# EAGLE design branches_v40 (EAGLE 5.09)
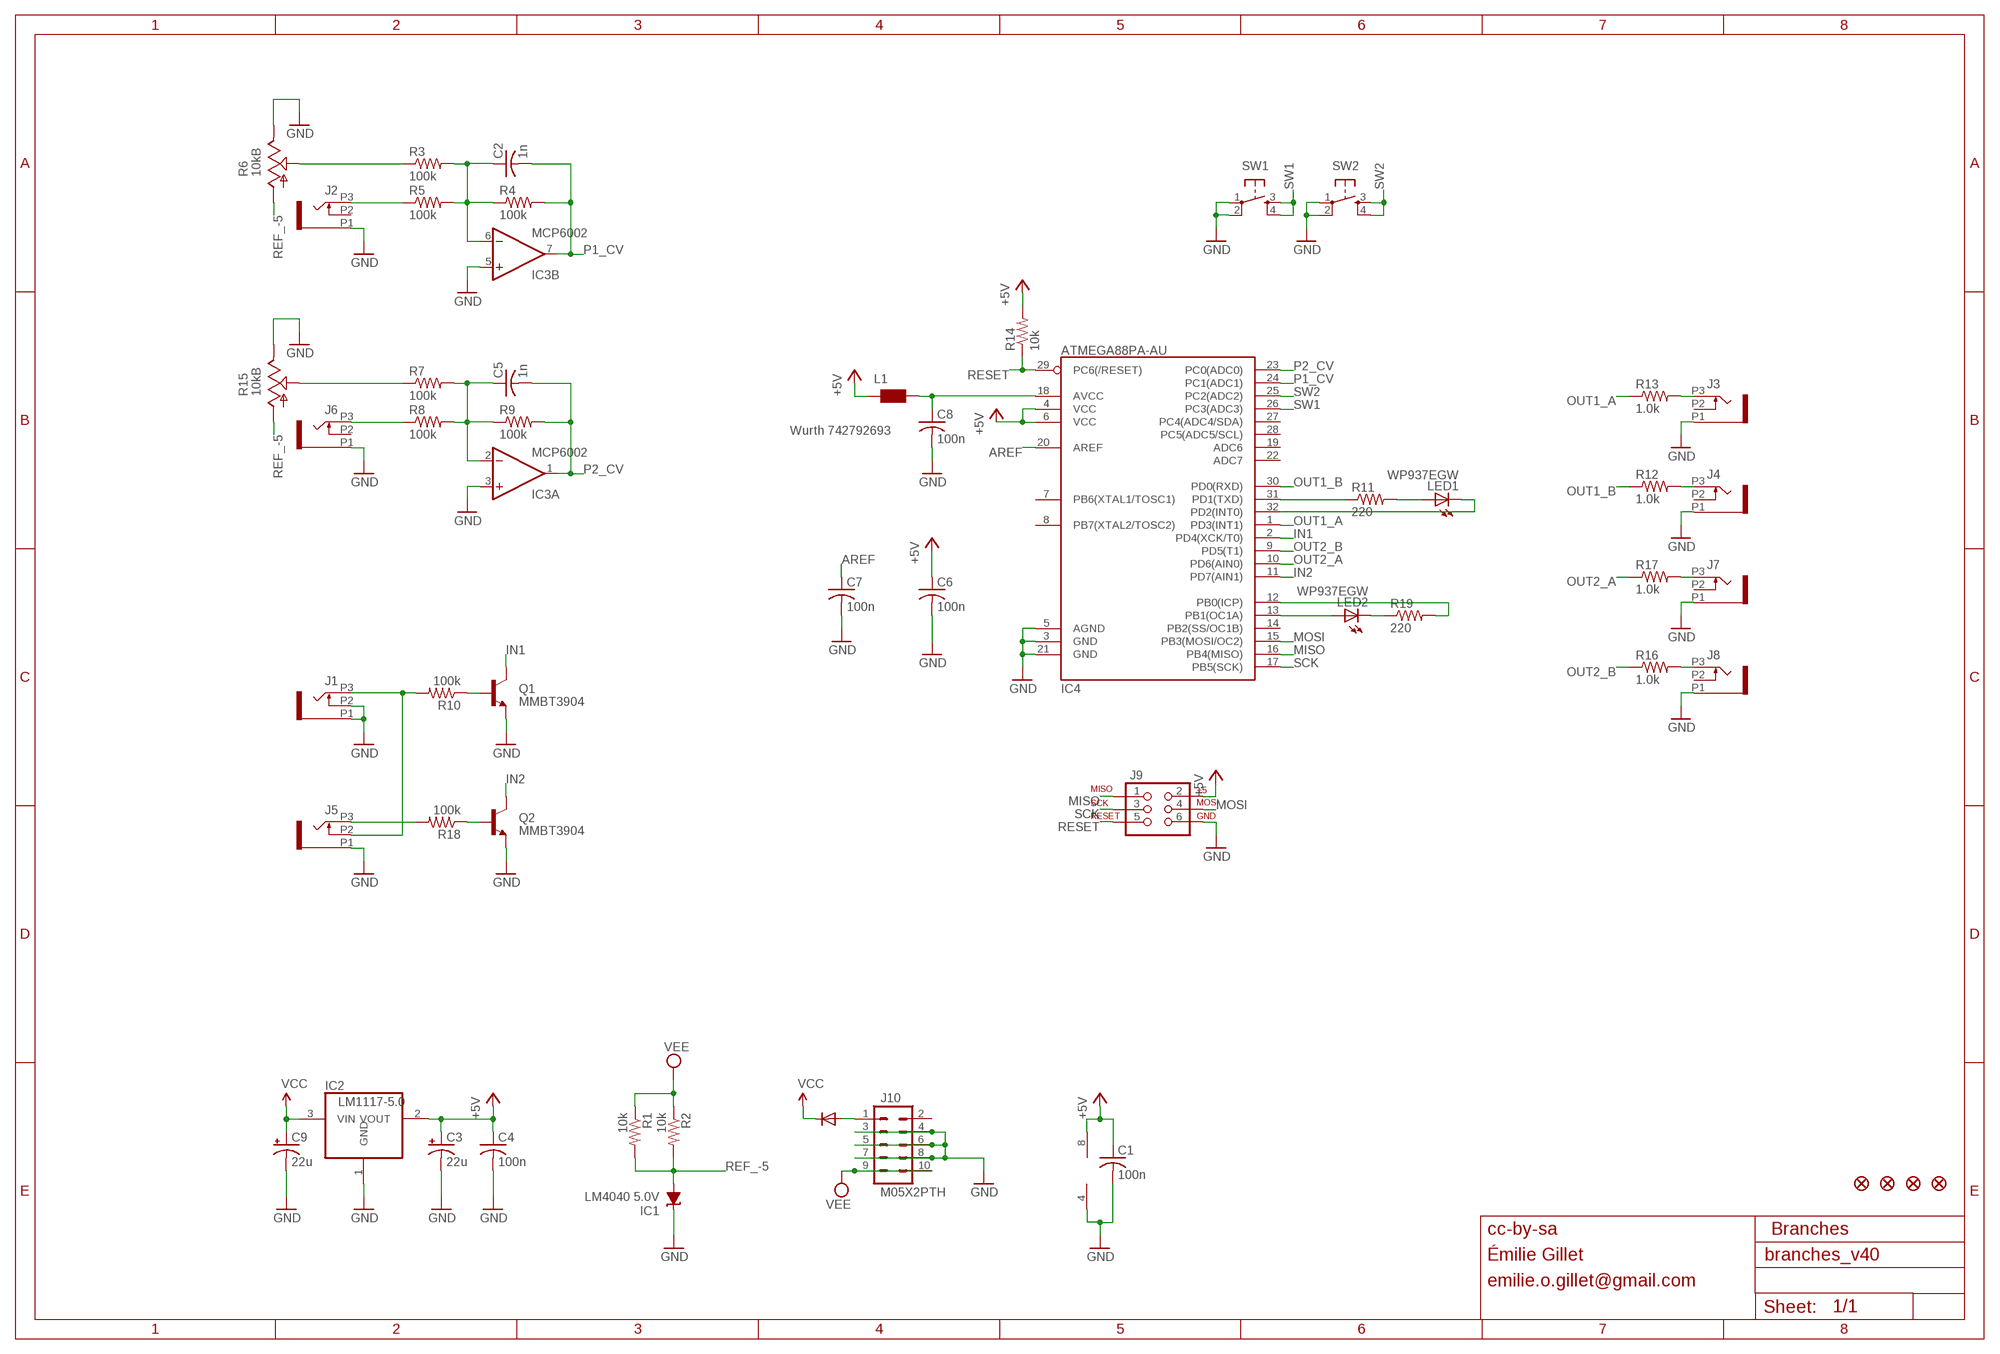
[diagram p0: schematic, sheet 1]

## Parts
C1  100n  C-USC0603  [C0603]
C2  1n  C-USC0603  [C0603]
C3  22u  CPOL-USC  [PANASONIC_C]
C4  100n  C-USC0603  [C0603]
C5  1n  C-USC0603  [C0603]
C6  100n  C-USC0603  [C0603]
C7  100n  C-USC0603  [C0603]
C8  100n  C-USC0603  [C0603]
C9  22u  CPOL-USC  [PANASONIC_C]
D1  1N5819HW  DIODE-SOD123  [SOD123]
F1  FIDUCIAL1X2  [FIDUCIAL-1X2]
F2  FIDUCIAL1X2  [FIDUCIAL-1X2]
F3  FIDUCIAL1X2  [FIDUCIAL-1X2]
F4  FIDUCIAL1X2  [FIDUCIAL-1X2]
IC1  LM4040 5.0V  LM4041C12DBZ  [DBZ_R-PDSO-G3]
IC2  LM1117-5.0  REG1117  [SOT223]
IC3  MCP6002  TL072D  [SO08]
IC4  ATMEGA88PA-AU  ATMEGA168  [TQFP32-08]
J1  PJ301_THONKICONN6  [WQP_PJ_301M6]
J2  PJ301_THONKICONN6  [WQP_PJ_301M6]
J3  PJ301_THONKICONN6  [WQP_PJ_301M6]
J4  PJ301_THONKICONN6  [WQP_PJ_301M6]
J5  PJ301_THONKICONN6  [WQP_PJ_301M6]
J6  PJ301_THONKICONN6  [WQP_PJ_301M6]
J7  PJ301_THONKICONN6  [WQP_PJ_301M6]
J8  PJ301_THONKICONN6  [WQP_PJ_301M6]
J9  AVR_SPI_PRG_6PTH  [2X3]
J10  M05X2PTH  [AVR_ICSP]
L1  WE-CBF_0603  [0603]
LED1  WP937EGW  LED3MM  [LED3MM]
LED2  WP937EGW  LED3MM  [LED3MM]
Q1  MMBT3904  MMBT3904LT1-NPN-SOT23-BEC  [SOT23-BEC]
Q2  MMBT3904  MMBT3904LT1-NPN-SOT23-BEC  [SOT23-BEC]
R1  10k  R-US_R0603  [R0603]
R2  10k  R-US_R0603  [R0603]
R3  100k  R-US_R0603  [R0603]
R4  100k  R-US_R0603  [R0603]
R5  100k  R-US_R0603  [R0603]
R6  10kB  POT_USVERTICAL_PS  [ALPS_POT_VERTICAL_PS]
R7  100k  R-US_R0603  [R0603]
R8  100k  R-US_R0603  [R0603]
R9  100k  R-US_R0603  [R0603]
R10  100k  R-US_R0603  [R0603]
R11  220  R-US_R0603  [R0603]
R12  1.0k  R-US_R0603  [R0603]
R13  1.0k  R-US_R0603  [R0603]
R14  10k  R-US_R0603  [R0603]
R15  10kB  POT_USVERTICAL_PS  [ALPS_POT_VERTICAL_PS]
R16  1.0k  R-US_R0603  [R0603]
R17  1.0k  R-US_R0603  [R0603]
R18  100k  R-US_R0603  [R0603]
R19  220  R-US_R0603  [R0603]
SW1  TAC_SWITCHPTH  [TACTILE-PTH]
SW2  TAC_SWITCHPTH  [TACTILE-PTH]

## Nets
+5V: C1.1 C3.+ C4.1 C6.1 IC2.2(VOUT) IC3.8(P:V+) IC4.4(VCC) IC4.6(VCC) J9.2 L1.1 R14.2
AREF: C7.1 IC4.20(AREF)
GATE1_IN: J1.P3 J5.P2 R10.2
GATE2_IN: J5.P3 R18.2
GND: C1.2 C3.- C4.2 C6.2 C7.2 C8.2 C9.- IC1.1(C) IC2.1(GND) IC3.3(A:+IN) IC3.4(P:V-) IC3.5(B:+IN) IC4.3(GND) IC4.5(AGND) IC4.21(GND) J1.P1 J1.P2 J2.P1 J3.P1 J4.P1 J5.P1 J6.P1 J7.P1 J8.P1 J9.6 J10.3 J10.4 J10.5 J10.6 J10.7 J10.8 Q1.E Q2.E R6.P$1(E) R15.P$1(E) SW1.1 SW1.2 SW2.1 SW2.2
IN1: IC4.2(PD4(XCK/T0)) Q1.C
IN2: IC4.11(PD7(AIN1)) Q2.C
MISO: IC4.16(PB4(MISO)) J9.1
MOSI: IC4.15(PB3(MOSI/OC2)) J9.4
N$1: Q1.B R10.1
N$2: Q2.B R18.1
N$3: D1.A J10.1
N$4: C5.1 IC3.2(A:-IN) R7.2 R8.2 R9.1
N$6: J8.P3 R16.2
N$8: R7.1 R15.P$2(S)
N$9: R3.1 R6.P$2(S)
N$10: J2.P3 R5.1
N$11: J6.P3 R8.1
N$13: IC4.31(PD1(TXD)) R11.1
N$14: LED1.A R11.2
N$15: IC4.32(PD2(INT0)) LED1.K(C)
N$16: IC4.13(PB1(OC1A)) LED2.A
N$17: LED2.K(C) R19.1
N$18: IC4.12(PB0(ICP)) R19.2
N$29: C2.1 IC3.6(B:-IN) R3.2 R4.1 R5.2
N$34: J3.P3 R13.2
N$35: J4.P3 R12.2
N$36: J7.P3 R17.2
N$39: C8.1 IC4.18(AVCC) L1.2
OUT1_A: IC4.1(PD3(INT1)) R13.1
OUT1_B: IC4.30(PD0(RXD)) R12.1
OUT2_A: IC4.10(PD6(AIN0)) R17.1
OUT2_B: IC4.9(PD5(T1)) R16.1
P1_CV: C2.2 IC3.7(B:OUT) IC4.24(PC1(ADC1)) R4.2
P2_CV: C5.2 IC3.1(A:OUT) IC4.23(PC0(ADC0)) R9.2
REF_-5: IC1.2(A) R1.2 R2.2 R6.P$3(A) R15.P$3(A)
RESET: IC4.29(PC6(/RESET)) J9.5 R14.1
SCK: IC4.17(PB5(SCK)) J9.3
SW1: IC4.26(PC3(ADC3)) SW1.3 SW1.4
SW2: IC4.25(PC2(ADC2)) SW2.3 SW2.4
VCC: C9.+ D1.C IC2.3(VIN)
VEE: J10.9 J10.10 R1.1 R2.1
Unconnected: IC4.7(PB6(XTAL1/TOSC1)) IC4.8(PB7(XTAL2/TOSC2)) IC4.14(PB2(SS/OC1B)) IC4.19(ADC6) IC4.22(ADC7) IC4.27(PC4(ADC4/SDA)) IC4.28(PC5(ADC5/SCL)) J2.P2 J3.P2 J4.P2 J6.P2 J7.P2 J8.P2 J10.2

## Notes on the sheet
- Wurth 742792693
- cc-by-sa | Branches
- Émilie Gillet
- emilie.o.gillet@gmail.com

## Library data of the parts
C1 C2 C4-C8 = rcl:C-US: CAPACITOR, American symbol
C3 C9 = rcl:CPOL-US: POLARIZED CAPACITOR, American symbol
D1 = diode:DIODE-: DIODE
F1-F4 = SparkFun:FIDUCIAL: Fiducial Alignment Points
IC1 = texas:LM4041: PRECISION MICROPOWER SHUNT VOLTAGE REFERENCE
IC2 = og-vreg:REG1117: 800mA and 1A Low Dropout (LDO) Positive Regulator 1.8V, 2.5V, 2.85V, 3.3V, 5V, and Adj
IC3 = og-linear:TL072: OP AMP
IC4 = SparkFun:ATMEGA168
J1-J8 = og-pj301:PJ301_THONKICONN
J9 = SparkFun:AVR_SPI_PRG_6: AVR ISP 6 Pin This is the reduced ISP connector for AVR programming. Common on Arduino. This footprint will take up less PCB space and can be used with a 10-pin to 6-pin adapter such as SKU: BOB-08508
J10 = og-header:M05X2: Header 5x2 Standard 10-pin dual row 0.1" header. Commonly used with AVR-ISP. Use with Spark Fun Electronics SKU: PRT-00778
L1 = wuerth-elektronik:WE-CBF: SMD EMI Suppression Ferrite Beads
LED1 LED2 = led:LED: LED
Q1 Q2 = transistor:*-NPN-: NPN Transistror BF959 corrected 2008.03.06
R1 R2 = resistor:R-US_: RESISTOR, American symbol
R3-R5 R7-R14 R16-R19 = rcl:R-US_: RESISTOR, American symbol
R6 R15 = pot-alps:POT_US
SW1 SW2 = SparkFun:TAC_SWITCH: Momentary Switch Button commonly used for reset or general input. Spark Fun Electronics SKU : COM-00097

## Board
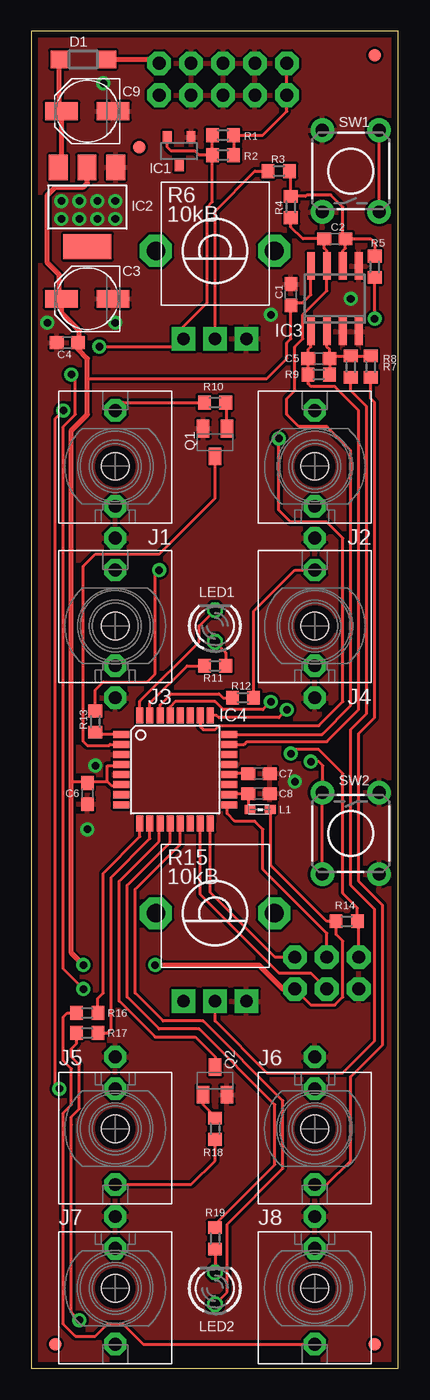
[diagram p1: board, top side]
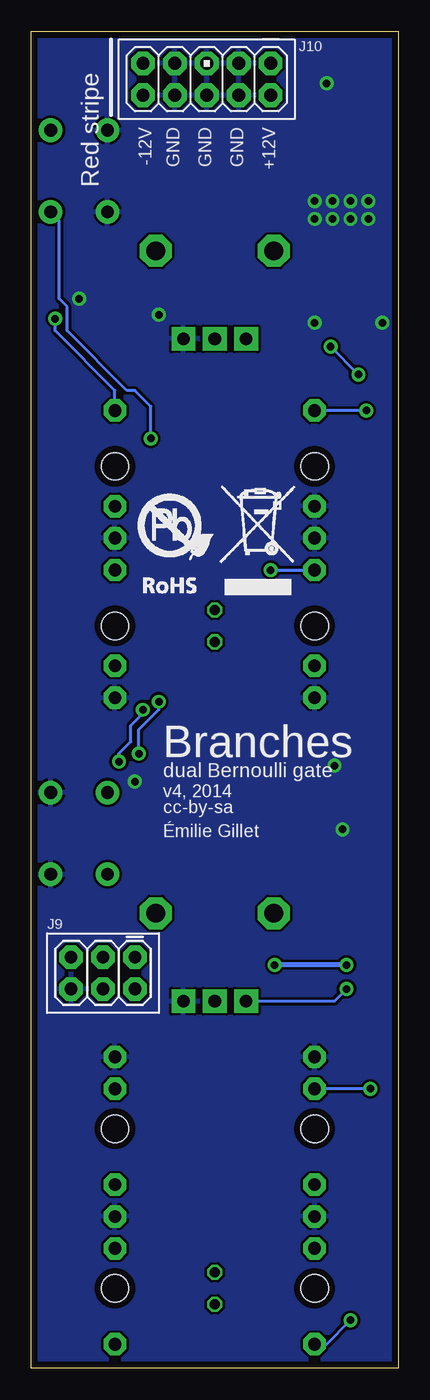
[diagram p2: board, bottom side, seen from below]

Size 29.19 x 106.36 mm. Coordinates in mm from the lower left corner, seen from the top.
Outline: 0,0 29.19,0 29.19,106.36 0,106.36 0,0
Copper layers (1*16): Top 0.035mm / dielectric 1.5mm / Bottom 0.035mm
Design rules "PCBCart-Standard *": minimum track width 8mil, minimum drill 0.4mm, track to track 8mil, track to pad 8mil, pad to pad 8mil, via to via 8mil, smd to smd 8mil, copper to edge 20mil, drill to drill 8mil, minimum pad ring 8mil, minimum via ring 10mil, stop-mask expansion 3mil, vias tented up to drill 25mil, thermal gap 8mil

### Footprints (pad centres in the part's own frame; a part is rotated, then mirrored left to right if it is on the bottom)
C0603 = smd 1.1 x 1: 1 -0.85,0; 2 0.85,0
PANASONIC_C = smd 2.6 x 1.4: + 2.05,0; - -2.05,0
SOD123 = smd 1.4 x 1.4: A 1.9,0; C -1.9,0
FIDUCIAL-1X2 = smd 1 x 1: 1 0,0
DBZ_R-PDSO-G3 = smd 0.7 x 1: 1 -0.95,-1.1; 2 0.95,-1.1; 3 0,1.1
SOT223 = smd 1.499 x 2.007: 1 -2.261,-3.15; 2 0.025,-3.15; 3 2.311,-3.15 | smd 3.81 x 2.007: 4 0,3.15
SO08 = smd 0.6 x 2.2: 1 -1.905,-2.6; 2 -0.635,-2.6; 3 0.635,-2.6; 4 1.905,-2.6; 5 1.905,2.6; 6 0.635,2.6; 7 -0.635,2.6; 8 -1.905,2.6
TQFP32-08 = smd 1.27 x 0.559: 1 -4.293,2.8; 2 -4.293,2; 3 -4.293,1.2; 4 -4.293,0.4; 5 -4.293,-0.4; 6 -4.293,-1.2; 7 -4.293,-2; 8 -4.293,-2.8; 17 4.293,-2.8; 18 4.293,-2; 19 4.293,-1.2; 20 4.293,-0.4; 21 4.293,0.4; 22 4.293,1.2; 23 4.293,2; 24 4.293,2.8 | smd 0.559 x 1.27: 9 -2.8,-4.293; 10 -2,-4.293; 11 -1.2,-4.293; 12 -0.4,-4.293; 13 0.4,-4.293; 14 1.2,-4.293; 15 2,-4.293; 16 2.8,-4.293; 25 2.8,4.293; 26 2,4.293; 27 1.2,4.293; 28 0.4,4.293; 29 -0.4,4.293; 30 -1.2,4.293; 31 -2,4.293; 32 -2.8,4.293
WQP_PJ_301M6 = drill 1.016 pad 1.778 octagon: P1 0,-5.715; P2 0,-3.175; P3 0,4.445 | hole 2.2: 0,0
2X3 = drill 1.016 pad 1.88 octagon: 1 0,0; 2 0,2.54; 3 2.54,0; 4 2.54,2.54; 5 5.08,0; 6 5.08,2.54
AVR_ICSP = drill 1.016 pad 1.88 octagon: 1 -1.27,5.08; 2 1.27,5.08; 3 -1.27,2.54; 4 1.27,2.54; 5 -1.27,0; 6 1.27,0; 7 -1.27,-2.54; 8 1.27,-2.54; 9 -1.27,-5.08; 10 1.27,-5.08
0603 = smd 0.85 x 0.7: 1 -0.9,0; 2 0.7,0
LED3MM = drill 0.813 octagon: A -1.27,0; K 1.27,0
SOT23-BEC = smd 1 x 1.4: B -0.95,-1.1; C 0,1.1; E 0.95,-1.1
R0603 = smd 1 x 1.1: 1 -0.85,0; 2 0.85,0
ALPS_POT_VERTICAL_PS = drill 1 pad 1.88 square: P$1 -2.5,7; P$2 0,7; P$3 2.5,7 | drill 1.5 pad 2.54 octagon: P$4 -4.7,0; P$5 4.7,0
TACTILE-PTH = drill 1.016 pad 1.88 round: 1 -3.251,2.261; 2 3.251,2.261; 3 -3.251,-2.261; 4 3.251,-2.261

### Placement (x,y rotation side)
C1  20.64,85.41 90 top
C2  24.13,89.85 180 top
C3  4.45,85.09 180 top
C4  2.86,81.6 180 top
C5  22.86,80.33 180 top
C6  4.45,45.72 270 top
C7  18.1,47.31 0 top
C8  18.1,45.72 0 top
C9  4.45,100.01 180 top
D1  4.13,104.14 0 top
F1  27.3,104.46 90 top
F2  8.57,97.16 90 top
F3  1.91,1.91 90 top
F4  27.3,1.91 90 top
IC1  11.75,96.84 180 top
IC2  4.45,92.39 180 top
IC3  24.13,85.09 0 top
IC4  11.43,47.62 0 top
J1  6.67,71.75 0 top
J2  22.54,71.75 0 top
J3  6.67,59.05 0 top
J4  22.54,59.05 0 top
J5  6.67,19.05 180 top
J6  22.54,19.05 180 top
J7  6.67,6.35 180 top
J8  22.54,6.35 180 top
J9  20.95,32.7 180 bottom
J10  15.24,102.55 270 bottom
L1  18.1,44.45 180 top
LED1  14.61,59.05 90 top
LED2  14.61,6.35 90 top
Q1  14.61,73.66 180 top
Q2  14.61,22.86 0 top
R1  15.24,98.11 180 top
R2  15.24,96.52 180 top
R3  19.68,95.25 0 top
R4  20.64,92.39 270 top
R5  27.3,87.63 90 top
R6  14.61,88.9 180 top
R7  25.4,79.69 90 top
R8  26.99,79.69 90 top
R9  22.86,79.06 180 top
R10  14.61,76.83 180 top
R11  14.61,55.88 0 top
R12  16.83,53.34 0 top
R13  5.08,51.44 90 top
R14  25.08,35.56 180 top
R15  14.61,36.2 180 top
R16  4.45,28.26 180 top
R17  4.45,26.67 180 top
R18  14.61,19.05 270 top
R19  14.61,10.32 90 top
SW1  25.4,95.25 90 top
SW2  25.4,42.55 270 top
U$1  [ROHS]  21.59,60.96 0 bottom

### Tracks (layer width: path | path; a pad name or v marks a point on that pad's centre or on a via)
+5V  (via drill 0.6)
  Top 0.254: IC4.4 7.05,47.94 6.03,47.94 6.03,46.67 | IC4.6 7.07,46.35 6.35,46.35 6.03,46.67 | 4.55,46.67 C6.1 | 3.17,46.67 4.55,46.67 | L1.1 19.05,44.4 19.05,40.01 23.5,35.56 R14.2 24.23,34.51 24.77,33.97 24.77,29.53 24.13,28.89 22.23,28.89 J9.2 | 4.45,78.74 18.73,78.74 20.32,80.33 20.32,81.6 20.64,81.92 C1.1 20.85,84.77 21.59,84.77 22.23,85.41 IC3.8 | 4.55,46.67 6.03,46.67
  Top 0.406: IC2.2 4.45,95.52 4.45,94.3 4.13,93.98 1.91,93.98 1.27,93.34 1.27,87.95 2.22,87 2.22,85.26 C3.+ | C3.+ 2.33,85.02 | v4.13,32.07 3.17,33.02 3.17,46.67 3.17,74.61 4.45,75.88 4.45,78.74 4.45,80.33 3.71,81.06 C4.1 3.81,81.7 3.81,82.55 2.4,83.97 C3.+ | v9.84,32.07 18.1,32.07 20,30.16 J9.2
  Bottom 0.406: v4.13,32.07 v9.84,32.07
AREF
  Top 0.254: IC4.20 15.8,47.31 C7.1
GATE1_IN  (via drill 0.6)
  Top 0.254: J1.P3 7.3,76.83 R10.2 | v2.54,76.2 1.91,75.56 1.91,22.54 v2.22,22.23
  Bottom 0.254: v2.54,76.2 J1.P3 | v2.22,22.23 J5.P2
GATE2_IN
  Top 0.254: 14.5,18.2 R18.2 14.61,16.51 12.7,14.61 J5.P3
GND  (via drill 0.6)
  other vias: 20.95,46.67 4.45,42.86 6.67,83.19 2.38,92.87 3.81,92.87 5.24,92.87 6.67,92.87 2.38,91.44 3.81,91.44 5.24,91.44 6.67,91.44 25.4,85.09 1.27,83.19 19.05,83.82 5.08,47.94 5.71,102.23
  pour Bottom: 0,106.36 0,0 29.21,0 29.21,106.36
  pour Top: 0,106.36 0,0 29.21,0 29.21,106.36
IN1
  Top 0.254: Q1.C 14.61,69.22 10.16,64.77 5.08,64.77 4.13,63.82 4.13,49.85 4.45,49.53 6.16,49.53 6.25,49.62 IC4.2
IN2
  Top 0.254: IC4.11 10.16,43.26 10.16,41.91 6.99,38.73 6.99,29.21 9.84,26.35 13.02,26.35 14.61,24.77 Q2.C
MISO
  Top 0.254: 14.39,43.5 IC4.16 14.23,37.84 19.37,32.7 J9.1
MOSI
  Top 0.254: 13.34,43.24 IC4.15 13.43,37.69 19.68,31.43 22.23,31.43 J9.4
N$1
  Top 0.254: R10.1 15.55,76.73 Q1.B
N$2
  Top 0.254: Q2.B 13.65,20.95 14.61,20 R18.1
N$3
  Top 0.406: J10.1 9.84,104.14 D1.A
N$4
  Top 0.254: C5.1 R9.1 | C5.1 23.93,80.54 R7.2 R8.2 | IC3.2 23.5,81.28 23.71,81.06 C5.1
N$6
  Top 0.254: R16.2 2.86,28.26 2.54,27.94 2.54,24.45 3.17,23.81 3.17,20.95 2.54,20.32 2.54,3.49 3.49,2.54 5.08,2.54 6.03,3.49 7.3,3.49 8.89,1.91 J8.P3
N$8
  Top 0.254: R15.P$2 14.61,27.62 18.73,23.5 24.77,23.5 27.3,26.04 27.3,36.51 25.4,38.42 25.4,50.8 26.67,52.07 26.67,76.52 25.4,77.79 R7.1
N$9
  Top 0.254: R6.P$2 14.61,92.08 17.78,95.25 R3.1
N$10  (via drill 0.6)
  Top 0.254: v27.3,83.5 R5.1
  Bottom 0.254: v27.3,83.5 27.3,82.55 22.54,77.79 J2.P3
N$11
  Top 0.254: J6.P3 23.5,14.61 25.4,16.51 25.4,23.18 27.94,25.72 27.94,36.83 26.04,38.73 26.04,50.48 27.3,51.75 27.3,76.83 26.99,77.15 R8.1
N$13
  Top 0.254: R11.1 12.38,55.88 9.43,52.93 IC4.31
N$14
  Top 0.254: LED1.A 15.46,56.94 R11.2
N$15
  Top 0.254: LED1.K 13.34,59.05 13.34,57.78 8.63,53.08 IC4.32
N$16
  Top 0.254: LED2.A 15.56,6.03 15.56,11.43 20,15.88 20,21.27 13.65,27.62 10.48,27.62 8.26,29.84 8.26,38.1 11.83,41.67 IC4.13
N$17
  Top 0.254: R19.1 LED2.K
N$18
  Top 0.254: R19.2 14.61,11.43 19.37,16.19 19.37,20.95 13.34,26.99 10.16,26.99 7.62,29.53 7.62,38.42 11.03,41.83 IC4.12
N$29
  Top 0.254: IC3.6 24.77,88.9 24.98,89.11 C2.1 | R5.2 27.3,89.53 26.99,89.85 C2.1 | C2.1 24.77,90.07 24.77,92.39 23.81,93.34 21.91,93.34 21.8,93.24 R4.1 20.64,95.15 R3.2
N$34  (via drill 0.6)
  Top 0.254: v10.16,63.5 9.84,63.18 9.84,55.24 9.21,54.61 5.71,54.61 5.08,53.98 R13.2
  Bottom 0.254: v10.16,63.5 J3.P3
N$35
  Top 0.254: J4.P3 20.95,63.5 17.68,60.22 R12.2
N$36  (via drill 0.6)
  Top 0.254: 3.81,26.45 R17.2 3.6,25.82 3.17,25.4 3.17,24.77 3.81,24.13 3.81,20.64 3.17,20 3.17,19.37 3.17,4.45 v3.81,3.81
  Bottom 0.254: v3.81,3.81 5.71,1.91 J7.P3
N$39
  Top 0.254: L1.2 17.25,44.6 C8.1 15.82,45.72 IC4.18
OUT1_A
  Top 0.254: 6.99,50.58 IC4.1 5.24,50.42 R13.1
OUT1_B
  Top 0.254: IC4.30 10.23,52.77 11.11,53.66 14.92,53.66 15.24,53.34 R12.1
OUT2_A
  Top 0.254: IC4.10 9.43,42.13 6.35,39.05 6.35,26.99 6.03,26.67 R17.1
OUT2_B
  Top 0.254: IC4.9 8.63,42.28 5.71,39.37 5.71,29.84 5.29,29.43 R16.1
P1_CV
  Top 0.254: IC4.24 23.12,50.42 25.4,52.7 25.4,73.03 23.5,74.93 21.27,74.93 20.32,75.88 20.32,77.15 20.95,77.79 20.95,81.28 21.59,81.92 21.59,83.82 23.5,85.72 IC3.7 23.5,88.9 23.28,89.11 C2.2 21.59,89.85 20.64,90.81 R4.2
P2_CV
  Top 0.254: IC4.23 16.92,49.62 17.14,49.85 23.5,49.85 26.04,52.39 26.04,76.2 24.13,78.11 22.23,78.11 22.01,78.32 R9.2 C5.2 22.01,81.06 22.23,81.28 IC3.1
REF_-5  (via drill 0.6)
  Top 0.254: 12.06,81.94 R6.P$3 | 12.06,81.94 12.06,82.87 13.97,84.77 13.97,92.39 14.39,92.81 R2.2 | v3.17,79.06 3.49,78.74 3.49,75.88 2.54,74.93 2.54,31.75 v4.13,30.16 | R2.2 R1.2 | IC1.2 10.79,97.16 11.11,96.84 13.02,96.84 13.34,96.52 R2.2 | 12.06,81.94 11.4,81.28 v5.4,81.28
  Bottom 0.254: R6.P$3 12.09,81.92 | v3.17,79.06 v5.4,81.28 | v4.13,30.16 5.09,29.2 R15.P$3
RESET  (via drill 0.6)
  Top 0.254: IC4.29 11.03,52.62 11.43,53.02 14.61,53.02 15.24,52.39 18.41,52.39 v19.05,53.02 | J9.5 26.04,35.46 R14.1 25.93,36.62 24.77,37.78 24.77,47.31 22.86,49.21 20.95,49.21 v20.64,48.9
  Bottom 0.254: v19.05,53.02 19.05,52.39 20.64,50.8 v20.64,48.9
SCK
  Top 0.254: IC4.17 15.56,44.66 15.56,44.13 16.19,43.5 17.78,43.5 18.41,42.86 18.41,39.69 23.5,34.61 J9.3
SW1  (via drill 0.6)
  Top 0.254: SW1.3 SW1.4 | 13.34,51.82 IC4.26 13.43,51.02 13.65,50.8 14.61,50.8 14.92,51.12 22.86,51.12 24.77,53.02 24.77,66.04 23.5,67.31 20.64,67.31 19.68,68.26 v19.68,73.98
  Bottom 0.254: SW1.3 26.99,91.33 26.99,85.09 26.35,84.45 26.35,82.55 21.59,77.79 20.95,77.79 19.68,76.52 v19.68,73.98
SW2  (via drill 0.6)
  Top 0.254: SW2.4 SW2.3 23.18,45.83 23.18,47.94 22.86,48.26 v22.23,48.26 | v20.32,52.39 19.68,51.75 14.92,51.75 14.76,51.92 IC4.25
  Bottom 0.254: v20.32,52.39 20.32,52.07 21.27,51.12 21.27,49.85 22.23,48.9 v22.23,48.26
VCC
  Top 0.406: 2.45,103.92 D1.C 2.23,100.18 C9.+ 2.4,95.8 IC2.3
VEE
  Top 0.254: J10.9 J10.10 20.32,100.01 18.41,98.11 R1.1 R2.1

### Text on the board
bPlace: Red stripe
bNames: +12V | GND | GND | GND | -12V | Branches | dual Bernoulli gate | v4, 2014 | cc-by-sa | Émilie Gillet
